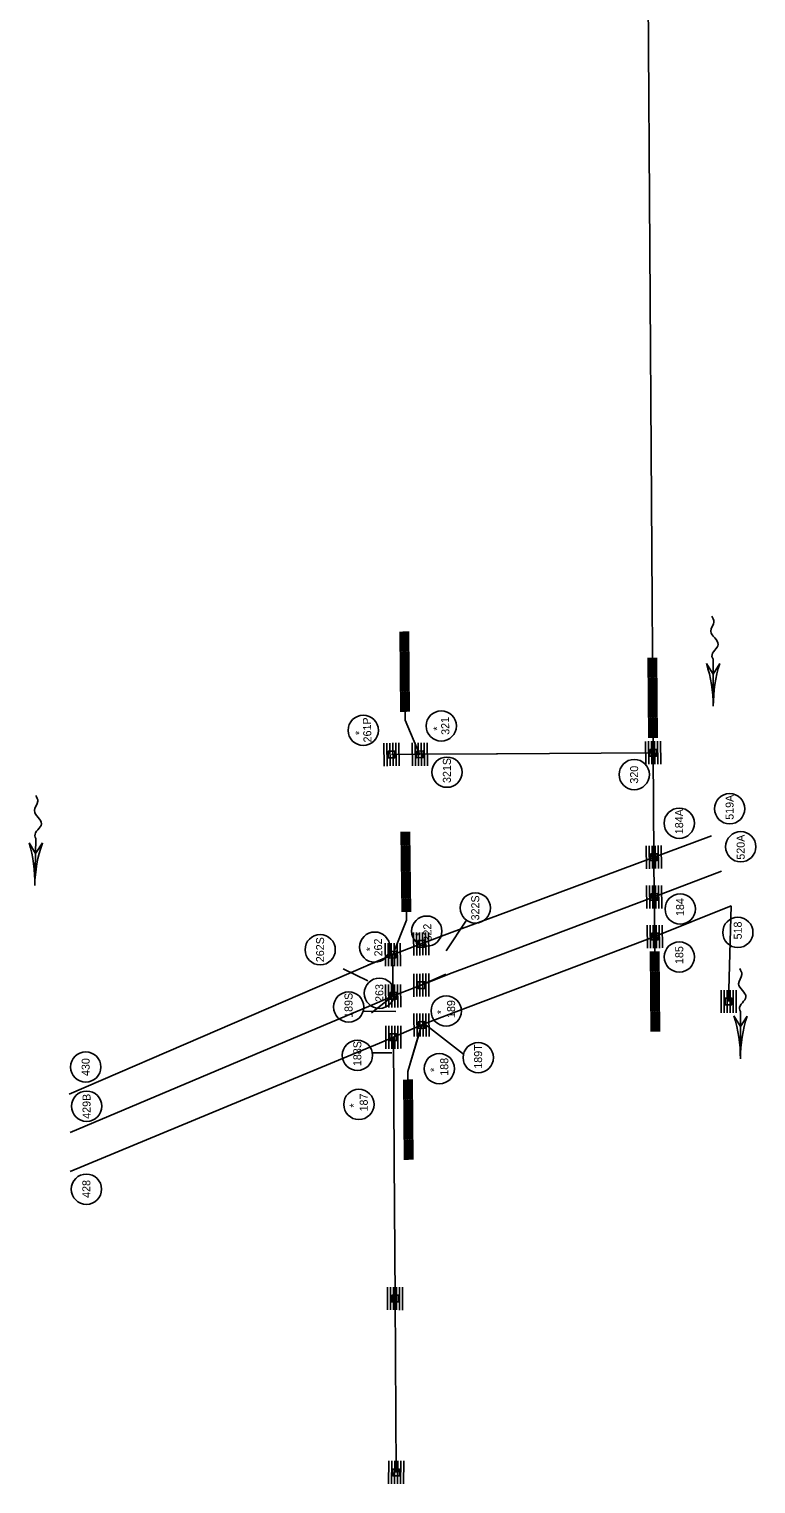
# Model space of a CAD drawing. Extents: x 593865 to 594193, y 188493 to 196452.
# Drawn here: x 593866.8 to 594084.8, y 194750 to 195186.3 of the extents above; entities that cross this region are included whole.
import ezdxf

# ---------------------------------------------------------------- set-up
doc = ezdxf.new("R2010")
doc.units = 0
for name, color, linetype in [('E_DRN', 7, 'Continuous'), ('P_DRN_Flow', 7, 'Continuous'), ('P_DRN_SS_UG_Stage2', 7, 'Continuous'), ('P_DRN_SS_UG_Stage2_AsExisting', 7, 'Continuous'), ('P_DRN_SS_UG_Stage3_AsExisting', 7, 'Continuous'), ('P_MISC_TXT_3A', 7, 'Continuous')]:
    doc.layers.add(name, color=color, linetype=linetype)

msp = doc.modelspace()

# ---------------------------------------------------------------- linework, layer by layer
at = {"layer": 'E_DRN'}
for p, q in [((593973.69, 194905.28), (593973.6, 194912.15)), ((593973.69, 194905.28), (593973.6, 194912.15)), ((593974.59, 194905.29), (593974.5, 194912.16)), ((593974.59, 194905.29), (593974.5, 194912.16)), ((593975.49, 194905.3), (593975.4, 194912.18)), ((593975.49, 194905.3), (593975.4, 194912.18)), ((593976.39, 194905.31), (593976.3, 194912.19)), ((593976.39, 194905.31), (593976.3, 194912.19)), ((593977.29, 194905.33), (593977.2, 194912.2)), ((593977.29, 194905.33), (593977.2, 194912.2)), ((593978.19, 194905.34), (593978.1, 194912.21)), ((593978.19, 194905.34), (593978.1, 194912.21)), ((593982.08, 194915.38), (593982.16, 194908.51)), ((593982.08, 194915.38), (593982.16, 194908.51)), ((593982.98, 194915.39), (593983.06, 194908.52)), ((593982.98, 194915.39), (593983.06, 194908.52)), ((593983.88, 194915.4), (593983.96, 194908.53)), ((593983.88, 194915.4), (593983.96, 194908.53)), ((593984.78, 194915.41), (593984.86, 194908.54)), ((593984.78, 194915.41), (593984.86, 194908.54)), ((593985.68, 194915.42), (593985.76, 194908.55)), ((593985.68, 194915.42), (593985.76, 194908.55)), ((593986.58, 194915.43), (593986.66, 194908.56)), ((593986.58, 194915.43), (593986.66, 194908.56)), ((593975.84, 194908.71), (593968.41, 194905.61)), ((593975.84, 194908.71), (593975.97, 194896.36)), ((593982.16, 194903.02), (593982.24, 194896.14)), ((593983.06, 194903.03), (593983.14, 194896.15)), ((593983.96, 194903.04), (593984.04, 194896.16)), ((593984.45, 194899.61), (593991.77, 194902.86)), ((593984.86, 194903.05), (593984.94, 194896.17)), ((593985.76, 194903.06), (593985.84, 194896.18)), ((593986.66, 194903.07), (593986.74, 194896.19)), ((593973.68, 194899.77), (593973.76, 194892.9)), ((593973.68, 194899.77), (593973.76, 194892.9)), ((593974.58, 194899.78), (593974.66, 194892.91)), ((593974.58, 194899.78), (593974.66, 194892.91)), ((593975.48, 194899.79), (593975.56, 194892.92)), ((593975.48, 194899.79), (593975.56, 194892.92)), ((593976.38, 194899.8), (593976.46, 194892.93)), ((593976.38, 194899.8), (593976.46, 194892.93)), ((593977.28, 194899.81), (593977.36, 194892.94)), ((593977.28, 194899.81), (593977.36, 194892.94)), ((593978.18, 194899.82), (593978.26, 194892.95)), ((593978.18, 194899.82), (593978.26, 194892.95)), ((594074.37, 194891.25), (594074.35, 194898.12)), ((594075.27, 194891.25), (594075.25, 194898.13)), ((594076.17, 194891.25), (594076.15, 194898.13)), ((594077.07, 194891.26), (594077.05, 194898.13)), ((594077.97, 194891.26), (594077.95, 194898.13)), ((594078.87, 194891.26), (594078.85, 194898.14)), ((593975.97, 194896.36), (593969.51, 194891.26)), ((593982.24, 194891.06), (593982.32, 194884.19)), ((593983.14, 194891.07), (593983.22, 194884.2)), ((593984.04, 194891.08), (593984.12, 194884.21)), ((593984.94, 194891.09), (593985.02, 194884.22)), ((593985.84, 194891.1), (593985.92, 194884.23)), ((593986.74, 194891.11), (593986.82, 194884.24)), ((593973.77, 194887.38), (593973.84, 194880.5)), ((593974.67, 194887.39), (593974.74, 194880.51)), ((593975.57, 194887.4), (593975.64, 194880.52)), ((593976.47, 194887.41), (593976.54, 194880.53)), ((593977.37, 194887.42), (593977.44, 194880.54)), ((593978.27, 194887.43), (593978.34, 194880.55)), ((593976.3, 194847.06), (593976.06, 194883.97)), ((593976.57, 194805.61), (593976.3, 194847.06)), ((593974.32, 194809.05), (593974.32, 194802.18)), ((593975.22, 194809.05), (593975.22, 194802.18)), ((593976.12, 194809.05), (593976.12, 194802.18)), ((593977.02, 194809.05), (593977.02, 194802.18)), ((593977.92, 194809.05), (593977.92, 194802.17)), ((593978.82, 194809.05), (593978.82, 194802.17)), ((593976.9, 194753.46), (593976.57, 194805.61)), ((593974.66, 194756.89), (593974.65, 194750.02)), ((593975.56, 194756.89), (593975.55, 194750.02)), ((593976.46, 194756.89), (593976.45, 194750.02)), ((593977.36, 194756.89), (593977.35, 194750.02)), ((593978.26, 194756.89), (593978.25, 194750.02)), ((593979.16, 194756.89), (593979.15, 194750.02))]:
    msp.add_line(p, q, dxfattribs=at)
for points in [[(593983.36, 194912.96), (593983.38, 194910.96), (593985.38, 194910.98), (593985.36, 194912.98)], [(593983.36, 194912.96), (593983.38, 194910.96), (593985.38, 194910.98), (593985.36, 194912.98)], [(593976.91, 194907.76), (593976.88, 194909.76), (593974.88, 194909.73), (593974.91, 194907.73)], [(593976.91, 194907.76), (593976.88, 194909.76), (593974.88, 194909.73), (593974.91, 194907.73)], [(593983.44, 194900.6), (593983.46, 194898.6), (593985.46, 194898.62), (593985.44, 194900.62)], [(593974.96, 194897.35), (593974.98, 194895.35), (593976.98, 194895.37), (593976.96, 194897.37)], [(593974.96, 194897.35), (593974.98, 194895.35), (593976.98, 194895.37), (593976.96, 194897.37)], [(594077.61, 194893.69), (594077.6, 194895.69), (594075.6, 194895.69), (594075.61, 194893.69)], [(593975.04, 194884.96), (593975.07, 194882.96), (593977.07, 194882.98), (593977.04, 194884.98)], [(593983.52, 194888.64), (593983.54, 194886.64), (593985.54, 194886.66), (593985.52, 194888.66)], [(593975.57, 194806.61), (593975.57, 194804.61), (593977.57, 194804.61), (593977.57, 194806.61)], [(593975.9, 194754.46), (593975.9, 194752.46), (593977.9, 194752.46), (593977.9, 194754.46)]]:
    msp.add_lwpolyline(points, close=True, dxfattribs=at)
at = {"layer": 'P_DRN_Flow'}
for p, q in [((594072.02, 194983.28), (594071.94, 194997.41)), ((593868.51, 194929.48), (593868.86, 194943.6)), ((594080.13, 194877.55), (594080.2, 194891.68))]:
    msp.add_line(p, q, dxfattribs=at)
for points in [[(594069.95, 194996.06), (594071.96, 194992.88), (594073.95, 194996.09)], [(593866.82, 194942.32), (593868.74, 194939.07), (593870.82, 194942.23)], [(594078.19, 194890.36), (594080.18, 194887.15), (594082.19, 194890.34)]]:
    msp.add_lwpolyline(points, dxfattribs=at)
for centre, start, end in [((594030.06, 194983.04), 0.3219, 18.0843), ((594113.98, 194983.52), 162.5596, 180.3219), ((593826.56, 194930.51), 358.5865, 16.3488), ((593910.45, 194928.44), 160.8242, 178.5865), ((594038.18, 194877.75), 359.7242, 17.4865), ((594122.09, 194877.35), 161.9619, 179.7242)]:
    msp.add_arc(centre, 41.96, start, end, dxfattribs=at)
for points in [[(594071.94, 194997.41), (594071.62, 194998.19), (594073.49, 195001.81), (594071.27, 195005.72), (594072.19, 195008.55), (594071.56, 195010.28)], [(593868.86, 194943.6), (593868.56, 194944.4), (593870.53, 194947.96), (593868.43, 194951.94), (593869.44, 194954.74), (593868.86, 194956.48)], [(594080.2, 194891.68), (594079.89, 194892.47), (594081.79, 194896.07), (594079.61, 194900), (594080.57, 194902.82), (594079.95, 194904.55)]]:
    msp.add_spline(points, degree=3, dxfattribs=at)
at = {"layer": 'P_DRN_SS_UG_Stage2'}
for p, q in [((594052.02, 195269.29), (594053.99, 194969.29)), ((593978.09, 195005.6), (593978.32, 194981.6)), ((593978.59, 195005.6), (593978.82, 194981.61)), ((593979.09, 195005.61), (593979.32, 194981.61)), ((593979.59, 195005.61), (593979.82, 194981.61)), ((593980.09, 195005.62), (593980.32, 194981.62)), ((593980.59, 195005.62), (593980.82, 194981.62)), ((594052.53, 194997.78), (594052.72, 194973.78)), ((594053.03, 194997.79), (594053.22, 194973.79)), ((594053.53, 194997.79), (594053.72, 194973.79)), ((594054.03, 194997.79), (594054.22, 194973.8)), ((594054.53, 194997.8), (594054.72, 194973.8)), ((594055.03, 194997.8), (594055.22, 194973.8)), ((593979.59, 194979.11), (593979.57, 194981.61)), ((593979.59, 194979.11), (593983.94, 194968.9)), ((593975.01, 194972.21), (593975.09, 194965.33)), ((593975.91, 194972.22), (593975.99, 194965.34)), ((593976.81, 194972.23), (593976.89, 194965.35)), ((593977.71, 194972.24), (593977.79, 194965.36)), ((593981.71, 194972.24), (593981.79, 194965.37)), ((593982.61, 194972.25), (593982.69, 194965.38)), ((593983.51, 194972.26), (593983.59, 194965.39)), ((593984.41, 194972.27), (593984.49, 194965.4)), ((593985.31, 194972.28), (593985.39, 194965.41)), ((593986.21, 194972.3), (593986.29, 194965.42)), ((594051.71, 194972.71), (594051.78, 194965.83)), ((594052.61, 194972.72), (594052.68, 194965.84)), ((594053.51, 194972.73), (594053.58, 194965.85)), ((594053.99, 194969.29), (594053.97, 194973.79)), ((594054.41, 194972.74), (594054.48, 194965.86)), ((594055.31, 194972.75), (594055.38, 194965.87)), ((594056.21, 194972.76), (594056.28, 194965.88)), ((593973.21, 194972.19), (593973.29, 194965.31)), ((593974.11, 194972.2), (593974.19, 194965.32)), ((593975.5, 194968.78), (593984, 194968.83)), ((593984, 194968.83), (594007, 194968.98)), ((594007, 194968.98), (594007.32, 194968.99)), ((594007.32, 194968.99), (594053.99, 194969.29)), ((594053.99, 194969.29), (594054.2, 194937.98)), ((593978.44, 194945.53), (593978.73, 194921.54)), ((593978.94, 194945.54), (593979.23, 194921.54)), ((593979.44, 194945.55), (593979.73, 194921.55)), ((593979.94, 194945.55), (593980.23, 194921.55)), ((593980.44, 194945.56), (593980.73, 194921.56)), ((593980.94, 194945.56), (593981.23, 194921.57)), ((594071.45, 194944.41), (594007.32, 194920.52)), ((594051.91, 194941.39), (594051.99, 194934.52)), ((594052.81, 194941.4), (594052.89, 194934.53)), ((594053.71, 194941.41), (594053.79, 194934.54)), ((594054.2, 194937.98), (594054.29, 194926.04)), ((594054.61, 194941.42), (594054.69, 194934.55)), ((594055.51, 194941.43), (594055.59, 194934.56)), ((594056.41, 194941.44), (594056.49, 194934.57)), ((594074.44, 194933.82), (594054.29, 194926.04)), ((594052, 194929.45), (594052.08, 194922.57)), ((594052.9, 194929.46), (594052.98, 194922.58)), ((594053.8, 194929.47), (594053.88, 194922.59)), ((594054.7, 194929.48), (594054.78, 194922.6)), ((594055.6, 194929.49), (594055.68, 194922.61)), ((594056.5, 194929.5), (594056.58, 194922.62)), ((594054.29, 194926.04), (594007.4, 194908.4)), ((594054.45, 194914.15), (594054.29, 194926.04)), ((593980.01, 194919.05), (593979.98, 194921.55)), ((594007.32, 194920.52), (593993.69, 194915.44)), ((594077.37, 194923.43), (594054.45, 194914.15)), ((594076.61, 194894.69), (594077.37, 194923.43)), ((593980.01, 194919.05), (593975.89, 194908.74)), ((594052.16, 194917.56), (594052.24, 194910.69)), ((594053.06, 194917.57), (594053.14, 194910.7)), ((594053.96, 194917.58), (594054.04, 194910.71)), ((594054.86, 194917.59), (594054.94, 194910.72)), ((594055.76, 194917.6), (594055.84, 194910.73)), ((594056.66, 194917.61), (594056.74, 194910.74)), ((593984.32, 194911.94), (593975.84, 194908.71)), ((593984.32, 194911.94), (593975.84, 194908.71)), ((593984.37, 194911.97), (593993.69, 194915.44)), ((593984.37, 194911.97), (593993.69, 194915.44)), ((594054.45, 194914.15), (594007.47, 194896.37)), ((594054.45, 194914.15), (594054.48, 194909.65)), ((593975.84, 194908.71), (593967.77, 194905.34)), ((594007.4, 194908.4), (593993.69, 194903.25)), ((594053.37, 194885.65), (594053.23, 194909.64)), ((594053.87, 194885.65), (594053.73, 194909.65)), ((594054.37, 194885.65), (594054.23, 194909.65)), ((594054.87, 194885.65), (594054.73, 194909.65)), ((594055.37, 194885.66), (594055.23, 194909.66)), ((594055.87, 194885.66), (594055.73, 194909.66)), ((593967.77, 194905.34), (593878.86, 194866.87)), ((593993.69, 194903.25), (593984.45, 194899.61)), ((593984.45, 194899.61), (593975.97, 194896.36)), ((593971.2, 194894.32), (593879.18, 194855.36)), ((593971.2, 194894.32), (593975.97, 194896.36)), ((594007.47, 194896.37), (593994.03, 194891.29)), ((593994.03, 194891.29), (593984.56, 194887.68)), ((593984.56, 194887.68), (593976.06, 194883.97)), ((593980.4, 194873.75), (593984.56, 194887.68)), ((593971.89, 194882.16), (593879.17, 194843.68)), ((593976.06, 194883.97), (593971.89, 194882.16)), ((593980.4, 194873.75), (593980.43, 194871.25)), ((593979.41, 194847.24), (593979.18, 194871.24)), ((593979.91, 194847.25), (593979.68, 194871.25)), ((593980.41, 194847.25), (593980.18, 194871.25)), ((593980.91, 194847.26), (593980.68, 194871.26)), ((593981.41, 194847.26), (593981.18, 194871.26)), ((593981.91, 194847.27), (593981.68, 194871.26))]:
    msp.add_line(p, q, dxfattribs=at)
for points in [[(593978.86, 194997.1), (593978.93, 194990.12), (593980.04, 194990.13), (593979.98, 194997.11)], [(594054.4, 194989.29), (594054.46, 194982.31), (594053.35, 194982.3), (594053.29, 194989.28)], [(593974.49, 194969.77), (593974.51, 194967.77), (593976.51, 194967.79), (593976.49, 194969.79)], [(593982.99, 194969.82), (593983.01, 194967.82), (593985.01, 194967.84), (593984.99, 194969.84)], [(594052.98, 194970.28), (594053.01, 194968.28), (594055.01, 194968.31), (594054.98, 194970.3)], [(594053.19, 194938.97), (594053.21, 194936.97), (594055.21, 194936.99), (594055.19, 194938.99)], [(593980.35, 194937.05), (593980.44, 194930.07), (593979.32, 194930.05), (593979.24, 194937.03)], [(594053.28, 194927.02), (594053.3, 194925.02), (594055.3, 194925.05), (594055.28, 194927.05)], [(594053.44, 194915.14), (594053.46, 194913.14), (594055.46, 194913.16), (594055.44, 194915.16)], [(594055.12, 194894.16), (594055.08, 194901.15), (594053.97, 194901.14), (594054.01, 194894.16)], [(593981.13, 194855.77), (593981.06, 194862.75), (593979.95, 194862.74), (593980.02, 194855.76)]]:
    msp.add_lwpolyline(points, close=True, dxfattribs=at)
at = {"layer": 'P_DRN_SS_UG_Stage2_AsExisting'}
for p, q in [((594052.02, 195269.29), (594053.99, 194969.29)), ((594052.53, 194997.78), (594052.72, 194973.78)), ((594053.03, 194997.79), (594053.22, 194973.79)), ((594053.53, 194997.79), (594053.72, 194973.79)), ((594054.03, 194997.79), (594054.22, 194973.8)), ((594054.53, 194997.8), (594054.72, 194973.8)), ((594055.03, 194997.8), (594055.22, 194973.8)), ((594051.71, 194972.71), (594051.78, 194965.83)), ((594052.61, 194972.72), (594052.68, 194965.84)), ((594053.51, 194972.73), (594053.58, 194965.85)), ((594053.99, 194969.29), (594053.97, 194973.79)), ((594054.41, 194972.74), (594054.48, 194965.86)), ((594055.31, 194972.75), (594055.38, 194965.87)), ((594056.21, 194972.76), (594056.28, 194965.88)), ((594007.32, 194968.99), (594053.99, 194969.29)), ((594053.99, 194969.29), (594054.2, 194937.98)), ((594071.45, 194944.41), (594007.32, 194920.52)), ((594051.91, 194941.39), (594051.99, 194934.52)), ((594052.81, 194941.4), (594052.89, 194934.53)), ((594053.71, 194941.41), (594053.79, 194934.54)), ((594054.2, 194937.98), (594054.29, 194926.04)), ((594054.61, 194941.42), (594054.69, 194934.55)), ((594055.51, 194941.43), (594055.59, 194934.56)), ((594056.41, 194941.44), (594056.49, 194934.57)), ((594074.44, 194933.82), (594054.29, 194926.04)), ((594052, 194929.45), (594052.08, 194922.57)), ((594052.9, 194929.46), (594052.98, 194922.58)), ((594053.8, 194929.47), (594053.88, 194922.59)), ((594054.7, 194929.48), (594054.78, 194922.6)), ((594055.6, 194929.49), (594055.68, 194922.61)), ((594056.5, 194929.5), (594056.58, 194922.62)), ((594054.29, 194926.04), (594007.4, 194908.4)), ((594054.45, 194914.15), (594054.29, 194926.04)), ((594077.37, 194923.43), (594054.45, 194914.15)), ((594076.61, 194894.69), (594077.37, 194923.43)), ((594052.16, 194917.56), (594052.24, 194910.69)), ((594053.06, 194917.57), (594053.14, 194910.7)), ((594053.96, 194917.58), (594054.04, 194910.71)), ((594054.86, 194917.59), (594054.94, 194910.72)), ((594055.76, 194917.6), (594055.84, 194910.73)), ((594056.66, 194917.61), (594056.74, 194910.74)), ((593984.32, 194911.94), (593975.84, 194908.71)), ((593984.32, 194911.94), (593975.84, 194908.71)), ((593984.37, 194911.97), (593993.69, 194915.44)), ((593984.37, 194911.97), (593993.69, 194915.44)), ((594054.45, 194914.15), (594007.47, 194896.37)), ((593975.84, 194908.71), (593967.77, 194905.34)), ((593993.69, 194903.25), (593984.45, 194899.61)), ((593984.45, 194899.61), (593975.97, 194896.36)), ((593971.2, 194894.32), (593975.97, 194896.36)), ((593994.03, 194891.29), (593984.56, 194887.68)), ((593984.56, 194887.68), (593976.06, 194883.97)), ((593976.06, 194883.97), (593971.89, 194882.16))]:
    msp.add_line(p, q, dxfattribs=at)
for points in [[(594054.4, 194989.29), (594054.46, 194982.31), (594053.35, 194982.3), (594053.29, 194989.28)], [(594052.98, 194970.28), (594053.01, 194968.28), (594055.01, 194968.31), (594054.98, 194970.3)], [(594053.19, 194938.97), (594053.21, 194936.97), (594055.21, 194936.99), (594055.19, 194938.99)], [(594053.28, 194927.02), (594053.3, 194925.02), (594055.3, 194925.05), (594055.28, 194927.05)], [(594053.44, 194915.14), (594053.46, 194913.14), (594055.46, 194913.16), (594055.44, 194915.16)]]:
    msp.add_lwpolyline(points, close=True, dxfattribs=at)
at = {"layer": 'P_DRN_SS_UG_Stage3_AsExisting'}
for p, q in [((593978.09, 195005.6), (593978.32, 194981.6)), ((593978.59, 195005.6), (593978.82, 194981.61)), ((593979.09, 195005.61), (593979.32, 194981.61)), ((593979.59, 195005.61), (593979.82, 194981.61)), ((593980.09, 195005.62), (593980.32, 194981.62)), ((593980.59, 195005.62), (593980.82, 194981.62)), ((593979.59, 194979.11), (593979.57, 194981.61)), ((593979.59, 194979.11), (593983.94, 194968.9)), ((593975.01, 194972.21), (593975.09, 194965.33)), ((593975.91, 194972.22), (593975.99, 194965.34)), ((593976.81, 194972.23), (593976.89, 194965.35)), ((593977.71, 194972.24), (593977.79, 194965.36)), ((593981.71, 194972.24), (593981.79, 194965.37)), ((593982.61, 194972.25), (593982.69, 194965.38)), ((593983.51, 194972.26), (593983.59, 194965.39)), ((593984.41, 194972.27), (593984.49, 194965.4)), ((593985.31, 194972.28), (593985.39, 194965.41)), ((593986.21, 194972.3), (593986.29, 194965.42)), ((593973.21, 194972.19), (593973.29, 194965.31)), ((593974.11, 194972.2), (593974.19, 194965.32)), ((593975.5, 194968.78), (593984, 194968.83)), ((593984, 194968.83), (594007, 194968.98)), ((594007, 194968.98), (594007.32, 194968.99)), ((593978.44, 194945.53), (593978.73, 194921.54)), ((593978.94, 194945.54), (593979.23, 194921.54)), ((593979.44, 194945.55), (593979.73, 194921.55)), ((593979.94, 194945.55), (593980.23, 194921.55)), ((593980.44, 194945.56), (593980.73, 194921.56)), ((593980.94, 194945.56), (593981.23, 194921.57)), ((593980.01, 194919.05), (593979.98, 194921.55)), ((594007.32, 194920.52), (593993.69, 194915.44)), ((593980.01, 194919.05), (593975.89, 194908.74)), ((594007.4, 194908.4), (593993.69, 194903.25)), ((594007.47, 194896.37), (593994.03, 194891.29)), ((593980.4, 194873.75), (593984.53, 194887.65)), ((593980.4, 194873.75), (593980.43, 194871.25)), ((593979.41, 194847.24), (593979.18, 194871.24)), ((593979.91, 194847.25), (593979.68, 194871.25)), ((593980.41, 194847.25), (593980.18, 194871.25)), ((593980.91, 194847.26), (593980.68, 194871.26)), ((593981.41, 194847.26), (593981.18, 194871.26)), ((593981.91, 194847.27), (593981.68, 194871.26))]:
    msp.add_line(p, q, dxfattribs=at)
for points in [[(593978.86, 194997.1), (593978.93, 194990.12), (593980.04, 194990.13), (593979.98, 194997.11)], [(593974.49, 194969.77), (593974.51, 194967.77), (593976.51, 194967.79), (593976.49, 194969.79)], [(593982.99, 194969.82), (593983.01, 194967.82), (593985.01, 194967.84), (593984.99, 194969.84)], [(593980.35, 194937.05), (593980.44, 194930.07), (593979.32, 194930.05), (593979.24, 194937.03)], [(593981.13, 194855.77), (593981.06, 194862.75), (593979.95, 194862.74), (593980.02, 194855.76)]]:
    msp.add_lwpolyline(points, close=True, dxfattribs=at)
at = {"layer": 'P_MISC_TXT_3A'}
for p, q in [((593998.03, 194919.04), (593991.88, 194909.84)), ((593968.45, 194900.93), (593961.01, 194904.48)), ((593967.03, 194891.83), (593976.83, 194891.73)), ((593984.52, 194888.66), (593997.09, 194878.85)), ((593969.76, 194879.33), (593975.64, 194879.26))]:
    msp.add_line(p, q, dxfattribs=at)
for centre in [(593990.43, 194977.33), (593967.04, 194976.01), (593992.15, 194963.47), (594048.3, 194962.75), (594076.93, 194952.5), (594061.81, 194948.16), (594080.25, 194941.11), (594000.65, 194922.75), (594062.09, 194922.44), (593986.08, 194915.79), (594079.38, 194915.42), (593970.49, 194910.99), (593954.12, 194910.22), (594061.83, 194908.05), (593971.88, 194897.17), (593962.65, 194893.05), (593991.91, 194891.85), (593965.28, 194878.56), (594001.52, 194877.85), (593883.81, 194875.05), (593989.85, 194874.54), (593884.08, 194863.29), (593965.72, 194863.83), (593884.01, 194838.4)]:
    msp.add_circle(centre, 4.54, dxfattribs=at)

# ---------------------------------------------------------------- texts
for s, rotation, p in [('261P', 91.7899, (593969.52, 194972.44)), ('*', 91.7899, (593990.44, 194975.97)), ('321', 91.7899, (593992.89, 194974.71)), ('*', 91.7899, (593967.05, 194974.65)), ('321S', 90, (593993.31, 194960.23)), ('320', 90, (594049.47, 194960.04)), ('519A', 90, (594078.1, 194949.19)), ('184A', 90, (594062.97, 194944.87)), ('520A', 90, (594081.42, 194937.23)), ('322S', 90, (594001.82, 194919.02)), ('184', 90, (594063.25, 194920.33)), ('322', 91.7899, (593987.56, 194912.72)), ('518', 90, (594080.55, 194913.31)), ('262S', 90, (593955.29, 194906.49)), ('262', 91.7899, (593972.78, 194908.26)), ('*', 91.7899, (593985.1, 194914.28)), ('185', 90, (594063, 194905.94)), ('*', 91.7899, (593970.33, 194909.81)), ('263', 90, (593973.05, 194894.57)), ('189S', 90, (593963.82, 194889.79)), ('189', 90, (593994.58, 194889.75)), ('*', 90, (593991.57, 194890.89)), ('188S', 90, (593966.45, 194875.32)), ('189T', 90, (594002.68, 194874.54)), ('430', 90, (593884.98, 194872.34)), ('188', 90, (593992.52, 194872.43)), ('*', 90, (593989.52, 194873.57)), ('429B', 90, (593885.25, 194859.52)), ('*', 90, (593965.39, 194862.87)), ('187', 90, (593968.39, 194861.72)), ('428', 90, (593885.18, 194835.8))]:
    msp.add_text(s, height=2.4, rotation=rotation, dxfattribs=at).set_placement(p)

doc.saveas('drawing.dxf')
